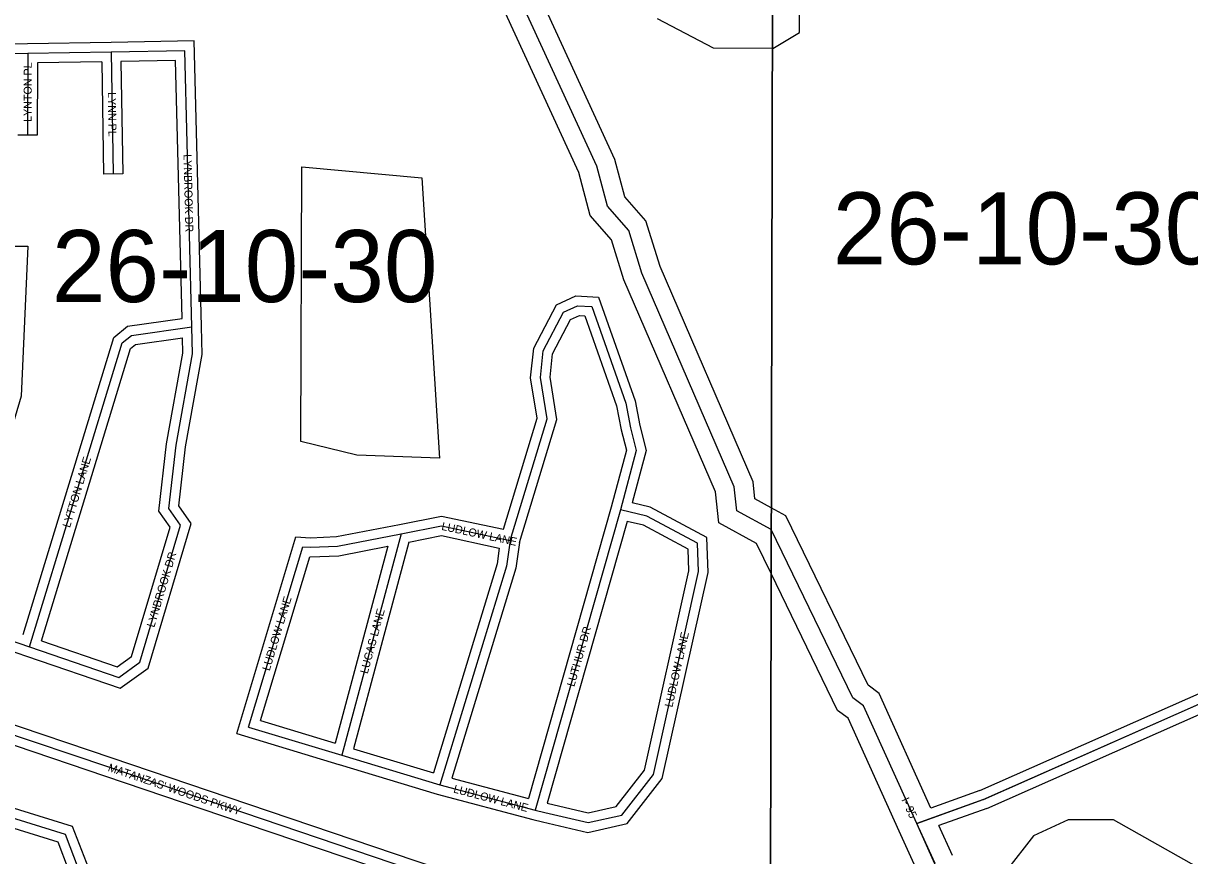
# Model space of a CAD drawing. Extents: x 457167 to 656239, y 1787309 to 1969297.
# Drawn here: x 574451 to 578095, y 1914444 to 1917044 of the extents above; entities that cross this region are included whole.
import ezdxf

# ---------------------------------------------------------------- set-up
doc = ezdxf.new("R2010")
doc.units = 0
for name, color, linetype in [('Level 13', 7, 'Continuous'), ('Level 14', 7, 'Continuous'), ('Level 2', 7, 'Continuous'), ('Level 31', 7, 'Continuous'), ('Level 32', 7, 'Continuous'), ('Level 34', 7, 'Continuous'), ('Level 5', 7, 'Continuous'), ('Level 63', 7, 'Continuous'), ('Level 7', 7, 'Continuous'), ('Level 8', 7, 'Continuous')]:
    doc.layers.add(name, color=color, linetype=linetype)

msp = doc.modelspace()

# ---------------------------------------------------------------- linework, layer by layer
at = {"layer": 'Level 13'}
msp.add_line((577299.805, 1914418.602), (577242.231, 1914544.546), dxfattribs=at)
for points in [[(576787.847, 1915462.208), (576787.819, 1915462.266), (576680.526, 1915521.043), (576672.424, 1915595.971), (576384.022, 1916263.515), (576342.678, 1916397.061), (576276.104, 1916472.479), (576243.005, 1916597.644), (575778.987, 1917607.397), (575737.392, 1917624.215), (575604.965, 1917957.966), (575505.226, 1918125.095), (575463.888, 1918258.642), (575281.555, 1918584.139), (575198.789, 1918809.416), (574792.296, 1919652.507)], [(577242.231, 1914544.546), (577076.163, 1914911.455), (577042.846, 1914936.617), (576787.846, 1915462.208)]]:
    msp.add_lwpolyline(points, dxfattribs=at)
at = {"layer": 'Level 14'}
for p, q in [((577354.375, 1914443.548), (577311.458, 1914537.431)), ((577245.237, 1914393.656), (577187.663, 1914519.599))]:
    msp.add_line(p, q, dxfattribs=at)
for points in [[(576787.993, 1915530.586), (576736.814, 1915558.623), (576731.102, 1915611.441), (576440.385, 1916284.346), (576396.185, 1916427.112), (576330.48, 1916501.544), (576299.688, 1916617.991), (575823.56, 1917654.096), (575783.692, 1917670.215), (575658.96, 1917984.575), (575560.425, 1918149.686), (575519.332, 1918282.438), (575336.232, 1918609.304), (575254.103, 1918832.846), (574854.885, 1919660.849)], [(576787.554, 1915325.355), (576742.195, 1915418.845), (576624.24, 1915483.463), (576613.745, 1915580.502), (576327.66, 1916242.683), (576289.171, 1916367.011), (576221.726, 1916443.415), (576186.321, 1916577.297), (575734.413, 1917560.699), (575691.093, 1917578.215), (575550.971, 1917931.356), (575450.028, 1918100.503), (575408.444, 1918234.847), (575226.879, 1918558.973), (575143.475, 1918785.985), (574739.737, 1919623.364)], [(577286.509, 1914592.231), (577124.522, 1914950.121), (577090.527, 1914975.797), (576833.441, 1915505.688), (576787.992, 1915530.586)], [(577187.569, 1914519.805), (577027.804, 1914872.788), (576995.165, 1914897.438), (576787.553, 1915325.355)]]:
    msp.add_lwpolyline(points, dxfattribs=at)
at = {"layer": 'Level 31'}
for p, q in [((574465.067, 1916949.531), (574105.31, 1916943.416)), ((574465.067, 1916949.531), (574464.504, 1916694.253)), ((574725.669, 1916954.047), (574465.067, 1916949.531)), ((574955.761, 1916958.27), (574725.669, 1916954.047)), ((574725.669, 1916954.047), (574731.824, 1916573.298)), ((574977.706, 1916096.021), (574955.761, 1916958.27)), ((576316.962, 1915524.007), (576050.519, 1914586.017)), ((574815.232, 1915047.628), (574942.66, 1915475.721)), ((575631.925, 1915449.125), (575446.09, 1914757.151)), ((575155.165, 1914845.424), (575324.835, 1915408.338)), ((574207.248, 1915186.061), (574470.831, 1915095.66)), ((573986.84, 1914967.636), (574717.581, 1914720.563)), ((575155.165, 1914845.424), (575446.09, 1914757.151)), ((575446.09, 1914757.151), (575752.262, 1914664.846)), ((574717.581, 1914720.563), (575080.256, 1914597.946)), ((575752.262, 1914664.846), (576050.519, 1914586.017)), ((575080.256, 1914597.946), (575955.83, 1914301.853)), ((577450.556, 1914619.012), (577242.231, 1914544.546))]:
    msp.add_line(p, q, dxfattribs=at)
for points in [[(575971.934, 1915428.023), (576087.485, 1915808.145), (576066.471, 1915937.648), (576074.912, 1916020.176), (576139.052, 1916141.131), (576182.953, 1916161.765), (576226.804, 1916159.124), (576333.251, 1915856.706), (576348.341, 1915780.308), (576366.304, 1915709.723), (576316.962, 1915524.007)], [(574470.831, 1915095.66), (574759.9, 1916045.225), (574789.19, 1916068.798), (574977.706, 1916096.021)], [(574942.66, 1915475.721), (574905.591, 1915528.167), (574928.27, 1915725.576), (574979.745, 1916011.287), (574977.706, 1916096.021)], [(577450.556, 1914619.012), (579402.759, 1915482.919), (579711.372, 1915649.191), (581203.721, 1915779.952), (581470.875, 1915879.776)], [(576050.519, 1914586.017), (576080.695, 1914578.316), (576215.38, 1914546.751), (576320.945, 1914570.524), (576419.741, 1914697.586), (576560.94, 1915331.115), (576557.635, 1915419.486), (576399.23, 1915503.829), (576316.962, 1915524.007)], [(575631.925, 1915449.125), (575757.831, 1915473.942), (575971.934, 1915428.023)], [(575324.835, 1915408.338), (575348.031, 1915406.833), (575433.211, 1915410.283), (575631.925, 1915449.125)], [(575971.934, 1915428.023), (575960.639, 1915348.41), (575752.262, 1914664.846)], [(574470.831, 1915095.66), (574749.342, 1915000.499), (574815.232, 1915047.628)], [(572871.805, 1915041.401), (574581.413, 1914511.039), (574622.81, 1914402.946)]]:
    msp.add_lwpolyline(points, dxfattribs=at)
at = {"layer": 'Level 32'}
for p, q in [((574464.558, 1916979.526), (574104.8, 1916973.412)), ((574725.15, 1916984.043), (574464.548, 1916979.526)), ((574984.995, 1916988.811), (574725.119, 1916984.042)), ((575007.698, 1916096.784), (574984.995, 1916988.811)), ((574926.53, 1916927.726), (574756.151, 1916924.601)), ((574947.038, 1916121.903), (574926.529, 1916927.726)), ((574495.003, 1916920.043), (574494.505, 1916694.187)), ((574696.159, 1916923.53), (574495.004, 1916920.043)), ((574696.159, 1916923.53), (574701.827, 1916572.813)), ((574756.151, 1916924.601), (574761.82, 1916573.783)), ((574494.505, 1916694.187), (574434.505, 1916694.319)), ((574761.82, 1916573.783), (574701.827, 1916572.813)), ((576288.104, 1915532.204), (576029.71, 1914622.548)), ((574789.414, 1915066.045), (574909.749, 1915470.308)), ((574841.052, 1915029.209), (574975.573, 1915481.133)), ((576337.915, 1915487.977), (576087.8, 1914607.463)), ((575117.8, 1914825.41), (575302.99, 1915439.817)), ((575590.478, 1915410.453), (575425.153, 1914794.854)), ((575656.055, 1915423.302), (575482.611, 1914777.474)), ((575192.533, 1914865.436), (575346.68, 1915376.856)), ((574197.515, 1915157.683), (574461.099, 1915067.281)), ((573996.45, 1914996.056), (574727.191, 1914748.983)), ((573977.231, 1914939.215), (574707.972, 1914692.142)), ((575192.533, 1914865.436), (575425.153, 1914794.854)), ((575117.8, 1914825.41), (575437.379, 1914728.442)), ((575482.612, 1914777.473), (575732.287, 1914702.202)), ((574727.19, 1914748.983), (575089.865, 1914626.366)), ((575437.43, 1914728.426), (575744.098, 1914635.973)), ((574707.973, 1914692.142), (575070.648, 1914569.526)), ((575790.042, 1914685.891), (576029.71, 1914622.547)), ((575744.097, 1914635.973), (576042.853, 1914557.012)), ((577439.423, 1914646.891), (577286.509, 1914592.231)), ((575089.866, 1914626.366), (575965.441, 1914330.272)), ((575070.646, 1914569.526), (575919.451, 1914282.486)), ((577461.692, 1914591.131), (577311.459, 1914537.431))]:
    msp.add_line(p, q, dxfattribs=at)
for points in [[(574120.446, 1916347.188), (574465.129, 1916347.226), (574444.86, 1915879.525), (574244.214, 1915205.099)], [(575951.254, 1915463.141), (576056.756, 1915810.211), (576036.223, 1915936.756), (576045.663, 1916029.056), (576117.235, 1916164.026), (576177.118, 1916192.171), (576248.489, 1916187.874), (576362.265, 1915864.634), (576377.616, 1915786.919), (576397.302, 1915709.56), (576353.81, 1915545.859)], [(576001.312, 1915421.515), (576118.212, 1915806.08), (576096.72, 1915938.539), (576104.161, 1916011.296), (576160.868, 1916118.236), (576188.789, 1916131.358), (576205.119, 1916130.375), (576304.236, 1915848.778), (576319.067, 1915773.698), (576335.305, 1915709.886), (576288.104, 1915532.204)], [(574451.18, 1915134.115), (574733.891, 1916062.803), (574776.775, 1916097.317), (574947.039, 1916121.903)], [(574975.574, 1915481.133), (574936.703, 1915536.126), (574957.965, 1915721.2), (575009.81, 1916008.964), (575007.699, 1916096.742)], [(574507.98, 1915114.67), (574785.91, 1916027.647), (574801.604, 1916040.278), (574948.529, 1916061.495)], [(574909.748, 1915470.308), (574874.479, 1915520.208), (574898.575, 1915729.953), (574949.68, 1916013.61), (574948.529, 1916061.495)], [(577439.424, 1914646.891), (579389.554, 1915509.883), (579702.589, 1915678.537), (581197.039, 1915809.483), (581438.852, 1915899.836)], [(577461.691, 1914591.131), (579415.964, 1915455.955), (579720.154, 1915619.845), (581210.403, 1915750.421), (581457.444, 1915842.73)], [(576043.099, 1914556.948), (576073.561, 1914549.174), (576215.246, 1914515.969), (576338.028, 1914543.619), (576447.559, 1914684.487), (576591.065, 1915328.367), (576586.969, 1915437.856), (576410.02, 1915532.072), (576353.81, 1915545.859)], [(575626.124, 1915478.558), (575758.085, 1915504.571), (575951.254, 1915463.141)], [(575302.99, 1915439.817), (575348.396, 1915436.873), (575429.707, 1915440.166), (575626.171, 1915478.568)], [(576087.8, 1914607.463), (576087.828, 1914607.457), (576215.514, 1914577.534), (576303.863, 1914597.43), (576391.924, 1914710.686), (576530.817, 1915333.861), (576528.3, 1915401.117), (576388.441, 1915475.586), (576337.916, 1915487.977)], [(575656.055, 1915423.301), (575757.576, 1915443.315), (575938.304, 1915404.552)], [(575346.68, 1915376.856), (575347.667, 1915376.793), (575436.716, 1915380.401), (575590.478, 1915410.454)], [(575938.303, 1915404.552), (575931.263, 1915354.93), (575732.287, 1914702.202)], [(576001.313, 1915421.514), (575990.015, 1915341.89), (575790.042, 1914685.891)], [(574507.98, 1915114.671), (574744.44, 1915033.877), (574789.413, 1915066.045)], [(572880.693, 1915070.054), (574604.218, 1914535.376), (574654.476, 1914404.146)], [(574461.131, 1915067.271), (574754.245, 1914967.121), (574841.053, 1915029.209)], [(572890.774, 1915004.104), (574558.608, 1914486.702), (574591.144, 1914401.746)]]:
    msp.add_lwpolyline(points, dxfattribs=at)
at = {"layer": 'Level 5'}
msp.add_lwpolyline([(575751.7, 1915685.742), (575493.315, 1915694.9), (575318.38, 1915737.168), (575321.12, 1916595.779), (575696.157, 1916561.263), (575751.7, 1915685.742)], close=True, dxfattribs=at)
at = {"layer": 'Level 63'}
for points in [[(536942.563, 1878385.707), (576708.29, 1878279.4), (576805.546, 1923734.416), (537088.612, 1923840.983), (536942.563, 1878385.707)], [(576708.289, 1878279.4), (616473.709, 1878215.526), (616521.962, 1923670.374), (576805.545, 1923734.416), (576708.289, 1878279.4)]]:
    msp.add_lwpolyline(points, dxfattribs=at)
at = {"layer": 'Level 7'}
for points in [[(576792.443, 1916965.556), (576875.874, 1917015.478), (576876.071, 1917207.213), (576792.996, 1917474.069)], [(576431.355, 1917059.085), (576606.13, 1916966.795), (576789.524, 1916966.206)], [(578198.525, 1914363.111), (577856.959, 1914555.204), (577715.247, 1914555.364), (577606.806, 1914505.441), (577523.316, 1914397.169), (578130.53, 1913137.731)]]:
    msp.add_lwpolyline(points, dxfattribs=at)
at = {"layer": 'Level 8'}
msp.add_lwpolyline([(580167.522, 1908987.372), (580043.517, 1909254.378), (579826.509, 1909596.386), (579818.509, 1909655.386), (579585.501, 1910022.394), (579569.499, 1910097.396), (579444.496, 1910264.399), (578820.473, 1911373.423), (578330.455, 1912191.44), (578288.454, 1912316.443), (578064.445, 1912742.451), (578042.444, 1912791.453), (577299.413, 1914418.488), (577242.41, 1914544.491), (577450.412, 1914619.494), (579402.426, 1915482.525), (579711.428, 1915649.531), (581203.445, 1915779.541)], dxfattribs=at)

# ---------------------------------------------------------------- texts
at = {"layer": 'Level 2'}
for p in [(576980.019, 1916290.852), (574540.672, 1916172.992)]:
    msp.add_text('26-10-30', height=225, dxfattribs=at).set_placement(p)
at = {"layer": 'Level 34'}
for s, height, rotation, p in [('LYNTON PL', 25, 89.872875, (574477.095, 1916735.88)), ('LYNN PL', 25, 270.925306, (574715.195, 1916828.66)), ('LYNBROOK DR', 25, 271.457161, (574951.499, 1916634.509)), ('LYTTON LANE', 25, 73.067744, (574596.779, 1915466.467)), ('LUDLOW LANE', 25, 347.894203, (575756.016, 1915461.548)), ('LYNBROOK DR', 25, 73.422894, (574860.194, 1915154.869)), ('LUDLOW LANE', 25, 73.225761, (575220.609, 1915019.236)), ('LUCAS LANE', 25, 74.966597, (575526.94, 1915010.01)), ('LUTHUR DR', 25, 74.141583, (576172.527, 1914969.794)), ('LUDLOW LANE', 25, 77.434617, (576478.902, 1914905.572)), ("MATANZAS' WOODS PKWY", 24.99916, 341.319517, (574713.515, 1914708.745)), ('LUDLOW LANE', 25, 345.194528, (575793.142, 1914641.115)), ('I- 95', 25, 294.566592, (577193.923, 1914618.441))]:
    msp.add_text(s, height=height, rotation=rotation, dxfattribs=at).set_placement(p)

doc.saveas('drawing.dxf')
